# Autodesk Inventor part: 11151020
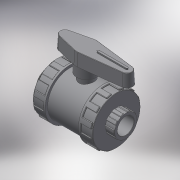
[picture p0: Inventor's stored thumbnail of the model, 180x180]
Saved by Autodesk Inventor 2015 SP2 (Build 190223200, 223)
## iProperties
Created: 2017-11
Part Number: 11151020
Material: Generic
Description: 2/NUT VALVE FEMALE THREAD 2" PVC
Document SubType Name: Modeling
Designer: KIM
Density: 1 g/cm^3
Appearance: Default
Author: KIM
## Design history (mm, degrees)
derived "111510.ipt"
feature "Solid1::111510.ipt"
tag "TaggingFeature1"
body "Solid1"
other parameters: "d0" = 169, "d1" = 56.656, "d2" = 118, "d3" = 26, "d4" = 45.3248, "d5" = 18.2, "d7" = 79.3184, "d8" = 106.2, "d13" = 1.69968, "d23" = 26, "d24" = 113.28, "d25" = 1.13312, "d26" = 1.69968, "d27" = 17.7, "d28" = 8.85, "d29" = 19.5, "d30" = 0, "d35" = 1.69968, "d39" = 59, "d45" = 360 deg, "d47" = 1.13312, "d50" = 64.9, "d51" = 35.4, "d53" = 0, "d55" = 11.3312, "d56" = 5.6656, "d57" = 18.2, "d58" = 0, "d59" = 1.69968, "d61" = 360 deg, "d63" = 47.2, "d64" = 106, "d66" = 129, "d68" = 23.6, "d69" = 38.7, "d70" = 26.5, "d71" = 3 deg, "d73" = 2.36, "d74" = 51.6, "d75" = 3.18, "d76" = 0, "d77" = 1.13312, "G_" = 56.656, "l_" = 26, "H_" = 169, "K_" = 118, "F_" = 106, "J_" = 129, "d67" = 47.2, "d72" = 11.8
